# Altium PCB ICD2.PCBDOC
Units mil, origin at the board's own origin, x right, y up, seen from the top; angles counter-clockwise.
Board outline 3890 x 2150 mil, 2 copper layers (Top Layer, Bottom Layer); 55 components, 63 nets, 194 pads, 14 vias.
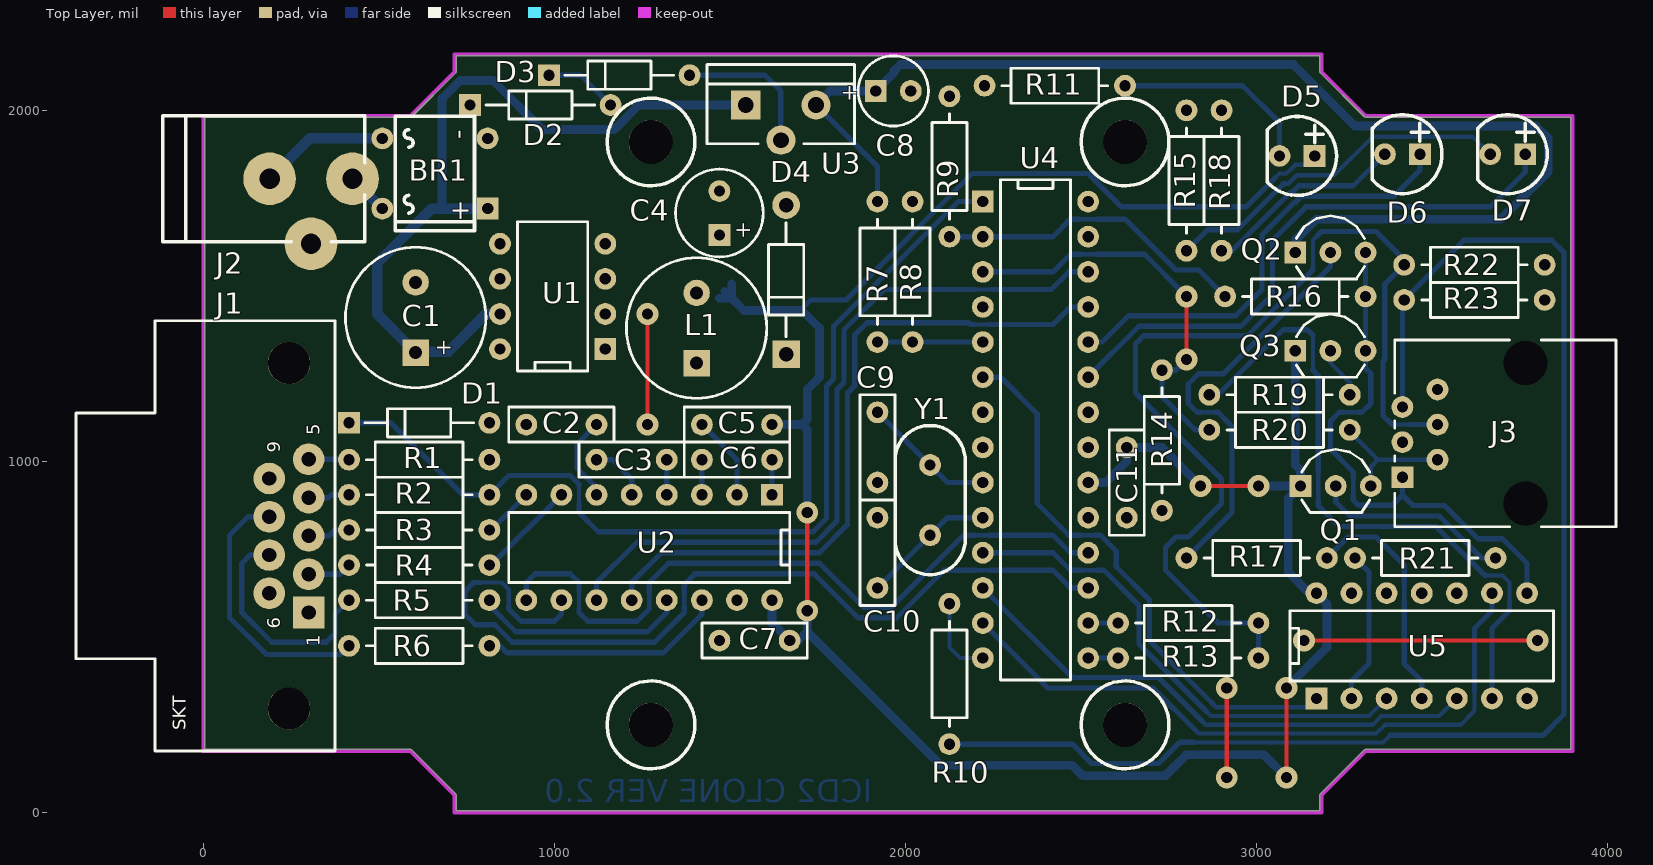
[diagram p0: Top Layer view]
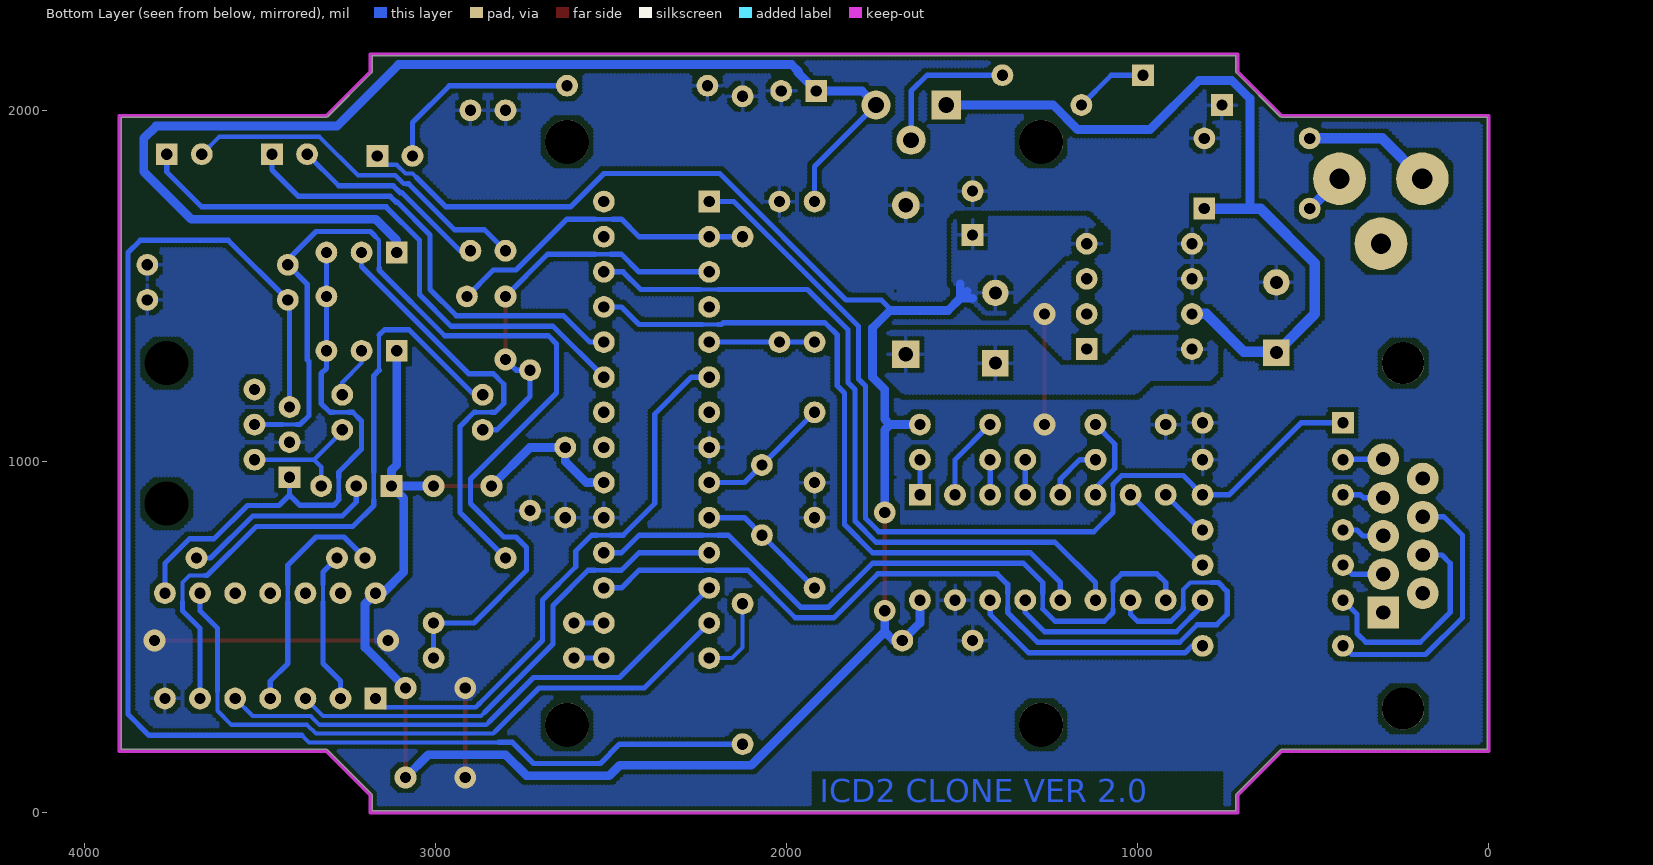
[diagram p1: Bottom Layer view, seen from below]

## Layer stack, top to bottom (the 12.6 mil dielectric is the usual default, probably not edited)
Top Layer: signal copper 1.4
Dielectric: dielectric 12.6, FR-4, Dk 4.8
Bottom Layer: signal copper 1.4

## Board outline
5,180 590,180 593.54,178.54 593.55,178.52 718.52,53.55 718.54,53.54 720,50 720,5 3180,5 3180,50 3181.46,53.54 3181.48,53.55 3306.45,178.52 3306.46,178.54 3310,180 3895,180 3895,1980 3310,1980 3306.46,1981.46 3306.45,1981.48 3181.48,2106.45 3181.46,2106.46 3180,2110 3180,2155 720,2155 720,2110 718.54,2106.46 718.52,2106.45 593.55,1981.48 593.54,1981.46 590,1980 5,1980

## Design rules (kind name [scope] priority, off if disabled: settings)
Clearance [All] p1: gap=12
ComponentClearance [All] p1: gap=10 collisioncheckmode=2
FanoutControl Fanout_Small [All] p1 off: bgadir=Out bgaviamode=Centered fanoutstyle=Auto fanoutdirection=Alternating viagrid=1 // Protel DXP Scope 1 Expression Was: (CompPinCount < 5)   Fanout_Small (Default Rule)
FanoutControl Fanout_Default [All] p2: bgadir=Out bgaviamode=Centered fanoutstyle=Auto fanoutdirection=Alternating viagrid=1 // Fanout_Default (Default Rule)
FanoutControl Fanout_SOIC [All] p3 off: bgadir=Out bgaviamode=Centered fanoutstyle=Auto fanoutdirection=Alternating viagrid=1 // Protel DXP Scope 1 Expression Was: IsSOIC   Fanout_SOIC (Default Rule)
FanoutControl Fanout_BGA [All] p4 off: bgadir=Out bgaviamode=Centered fanoutstyle=Auto fanoutdirection=Alternating viagrid=1 // Protel DXP Scope 1 Expression Was: IsBGA   Fanout_BGA (Default Rule)
FanoutControl Fanout_LCC [All] p5 off: bgadir=Out bgaviamode=Centered fanoutstyle=Auto fanoutdirection=Alternating viagrid=1 // Protel DXP Scope 1 Expression Was: IsLCC   Fanout_LCC (Default Rule)
HoleSize [All] p1: absolutevalues=TRUE maxlimit=150 minlimit=32 maxpercent=80.000 minpercent=20.000
PolygonConnect [All] p1: connectstyle=Relief reliefconductorwidth=10 reliefentries=4 polygonreliefangle="90 Angle"
RoomDefinition ICD2 [InComponentClass('ICD2')] p1: confinementstyle=ConfineIn formatcopy=TRUE outline 5,5 3900,5 3900,2155 5,2155
RoutingLayers [All] p1: top layer=Horizontal bottom layer=Vertical
RoutingVias [All] p1: holewidth=32 width=62 viastyle="Through Hole" minholewidth=28 minwidth=50 maxholewidth=32 maxwidth=62
SolderMaskExpansion [All] p1: expansion=4
TestPointUsage [All] p1: valid=0 allowmultiple=FALSE
Testpoint [All] p1: side=15 testpointundercomponent=TRUE minsize=40 maxsize=100 preferedsize=60 minholesize=0 maxholesize=40 preferedholesize=32 testpointgrid=1 style=1023 order=1234567890
Width [All] p1: maxlimit=50 minlimit=10 preferedwidth=10 toplayer_prefwidth=12 bottomlayer_prefwidth=15 minimp=50.000000 maximp=50.000000 favimp=50.000000
10 further rules are at their usual default settings.

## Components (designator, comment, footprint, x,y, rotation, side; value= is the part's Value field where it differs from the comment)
BR1 "BRIDGE" BRIDGE/DIP4 810,1720 r270 top
C1 "470u" CPCYL1/D.400/LS.200/.037 605,1310 r90 top
C2 "100n" RAD/.300X.100/LS.200/.032 1120,1105 r180 top
C3 "100n" RAD/.300X.100/LS.200/.032 1320,1005 r180 top
C4 "47uF" CPCYL1/D.250/LS.125/.032 1470,1645 r90 top
C5 "100n" RAD/.300X.100/LS.200/.032 1420,1105 r0 top
C6 "100n" RAD/.300X.100/LS.200/.032 1620,1005 r180 top
C7 "100n" RAD/.300X.100/LS.200/.032 1670,490 r180 top
C8 "10u" CPCYL1/D.200/LS.100/.032 1915,2055 r0 top
C9 "22p" RAD/.300X.100/LS.200/.032 1920,1140 r270 top
C10 "22p" RAD/.300X.100/LS.200/.032 1920,640 r90 top
C11 "100n" RAD/.300X.100/LS.200/.032 2630,1040 r270 top
D1 "5.1V" DAX2/.400X.080/.032 815,1110 r0 top
D2 "DIODE" DAX2/.400X.080/.032 1160,2015 r0 top
D3 "DIODE" DAX2/.400X.080/.032 1385,2100 r0 top
D4 "1N5819" DAX2/.425X.100/.041 1660,1730 r90 top
D5 "POWER" LED/ROND/5MM 3165,1870 r0 top
D6 "BUSY" LED/ROND/5MM 3465,1875 r0 top
D7 "ERROR" LED/ROND/5MM 3765,1875 r0 top
J1 "DB9" DSUB/RS.318/TM/9 300,570 r90 top locked
J2 "PJ102A" DC_POWER_JACK 425,1805 r180 top locked
J3 "TARGET" JACK1.27-2V6A 3590,1080 r90 top locked
L1 "220uH" CYL/D.400/LS.200/.037 1405,1280 r90 top
Q1 "2N4403" TO92/100 3125,930 r0 top
Q2 "2N4403" TO92/100 3110,1595 r0 top
Q3 "2N4403" TO92/100 3110,1315 r0 top
R1 "330R" AX/.400X.100/.032 415,1005 r0 top
R2 "1k" AX/.400X.100/.032 815,905 r180 top
R3 "330R" AX/.400X.100/.032 415,805 r0 top
R4 "330R" AX/.400X.100/.032 415,705 r0 top
R5 "330R" AX/.400X.100/.032 415,605 r0 top
R6 "330R" AX/.400X.100/.032 415,475 r0 top
R7 "6k8" AX/.400X.100/.032 1920,1340 r90 top
R8 "2k2" AX/.400X.100/.032 2020,1740 r270 top
R9 "2k2" AX/.400X.100/.032 2125,2040 r270 top
R10 "330R" AX/.400X.100/.032 2125,595 r270 top
R11 "300" AX/.400X.100/.032 2225,2070 r0 top
R12 "330R" AX/.400X.100/.032 2605,540 r0 top
R13 "330R" AX/.400X.100/.032 2605,440 r0 top
R14 "4k7" AX/.400X.100/.032 2730,860 r90 top
R15 "300" AX/.400X.100/.032 2800,2000 r270 top
R16 "6k8" AX/.400X.100/.032 2910,1470 r0 top
R17 "1k2" AX/.400X.100/.032 3200,725 r180 top
R18 "300" AX/.400X.100/.032 2900,2000 r270 top
R19 "390" AX/.400X.100/.032 2865,1190 r0 top
R20 "4k7" AX/.400X.100/.032 2865,1090 r0 top
R21 "130" AX/.400X.100/.032 3280,725 r0 top
R22 "4k7" AX/.400X.100/.032 3820,1560 r180 top
R23 "4k7" AX/.400X.100/.032 3820,1460 r180 top
U1 "LM2594N-5.0" DIP.100/8/W.300/L.425 1145,1320 r90 top
U2 "MAX232A" DIP.100/16/W.300/L.800 1620,905 r180 top
U3 "7812" TO220AB/VF1 1545,2015 r0 top
U4 "PIC16F876A" DIP.100/28/W.300/L1.425 2220,1740 r270 top
U5 "SN74LS07N" DIP.100/14/W.300/L.750 3170,325 r0 top
Y1 "20MHz" XTAL/HC49 2070,790 r90 top

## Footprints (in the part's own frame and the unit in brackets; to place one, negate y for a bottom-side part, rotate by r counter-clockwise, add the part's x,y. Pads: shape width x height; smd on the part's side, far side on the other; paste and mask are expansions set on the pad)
AX/.400X.100/.032 [mil]
  round 62 hole 32: 1(0,0) 2(400,0)
  silkscreen extent 50,-50 350,50
BRIDGE/DIP4 [mil]
  round 62 hole 32: AC1(-200,-300) AC2(0,-300) V-(-200,0)
  rect 62x62 hole 32: V+(0,0)
  silkscreen extent -262,-263 63,-37
CPCYL1/D.200/LS.100/.032 [mil]
  rect 62x62 hole 32: 1(0,0)
  round 62 hole 32: 2(100,0)
  silkscreen extent -50,-100 150,100
CPCYL1/D.250/LS.125/.032 [mil]
  rect 62x62 hole 32: 1(0,0)
  round 62 hole 32: 2(125,0)
  silkscreen extent -62,-125 188,125
CPCYL1/D.400/LS.200/.037 [mil]
  rect 75x75 hole 37: 1(0,0)
  round 75 hole 37: 2(200,0)
  silkscreen extent -100,-200 300,200
CYL/D.400/LS.200/.037 [mil]
  rect 75x75 hole 37: 1(0,0)
  round 75 hole 37: 2(200,0)
  silkscreen extent -100,-200 300,200
DAX2/.400X.080/.032 [mil]
  round 62 hole 32: 1(0,0)
  rect 62x62 hole 32: 2(-400,0)
  silkscreen extent -355,-40 -45,40
DAX2/.425X.100/.041 [mil]
  round 79 hole 41: 1(0,0)
  rect 79x79 hole 41: 2(-425,0)
  silkscreen extent -375,-50 -50,50
DC_POWER_JACK [mil]
  round 150 hole 58: 1(0,0) 2(236,0) 3(118,185)
  silkscreen extent -35,-180 540,180
DIP.100/8/W.300/L.425 [mil]
  rect 62x62 hole 32: 1(0,0)
  round 62 hole 32: 2(100,0) 3(200,0) 4(300,0) 5(300,300) 6(200,300) 7(100,300) 8(0,300)
  silkscreen extent -63,50 362,250
DIP.100/14/W.300/L.750 [mil]
  rect 62x62 hole 32: 1(0,0)
  round 62 hole 32: 2(100,0) 3(200,0) 4(300,0) 5(400,0) 6(500,0) 7(600,0) 8(600,300) 9(500,300) 10(400,300) 11(300,300) 12(200,300) 13(100,300) 14(0,300)
  silkscreen extent -75,50 675,250
DIP.100/16/W.300/L.800 [mil]
  rect 62x62 hole 32: 1(0,0)
  round 62 hole 32: 2(100,0) 3(200,0) 4(300,0) 5(400,0) 6(500,0) 7(600,0) 8(700,0) 9(700,300) 10(600,300) 11(500,300) 12(400,300) 13(300,300) 14(200,300) 15(100,300) 16(0,300)
  silkscreen extent -50,50 750,250
DIP.100/28/W.300/L1.425 [mil]
  rect 62x62 hole 32: 1(0,0)
  round 62 hole 32: 2(100,0) 3(200,0) 4(300,0) 5(400,0) 6(500,0) 7(600,0) 8(700,0) 9(800,0) 10(900,0) 11(1000,0) 12(1100,0) 13(1200,0) 14(1300,0) 15(1300,300) 16(1200,300) 17(1100,300) 18(1000,300) 19(900,300) 20(800,300) 21(700,300) 22(600,300) 23(500,300) 24(400,300) 25(300,300) 26(200,300) 27(100,300) 28(0,300)
  silkscreen extent -63,50 1362,250
DSUB/RS.318/TM/9 [mil]
  rect 90x90 hole 41: 1(0,0)
  round 90 hole 41: 2(109,0) 3(218,0) 4(327,0) 5(436,0) 6(54.5,112) 7(163.5,112) 8(272.5,112) 9(381.5,112)
  round 120 hole 120: 10(-274,56) 11(710,56)
  silkscreen extent -394,-76 830,662
JACK1.27-2V6A [mil]
  rect 62x62 hole 32: 1(-125,175)
  round 62 hole 32: 2(-75,75) 3(-25,175) 4(25,75) 5(75,175) 6(125,75)
  round 116.14 hole 125: MH1(-200,-175) MH2(200,-175)
  silkscreen extent -266,-433 266,197
LED/ROND/5MM [mil]
  rect 62x62 hole 32: 1(0,0)
  round 62 hole 32: 2(-100,0)
  silkscreen extent -135,-112 62,112
RAD/.300X.100/LS.200/.032 [mil]
  round 62 hole 32: 1(0,0) 2(200,0)
  silkscreen extent -50,-50 250,50
TO92/100 [mil]
  rect 62x62 hole 32: 1(0,0)
  round 62 hole 32: 2(100,0) 3(200,0)
  silkscreen extent 3,-75 197,105
TO220AB/VF1 [mil]
  rect 83x83 hole 45: 1(0,0)
  round 83 hole 45: 2(100,-100) 3(200,0)
  silkscreen extent -110,-110 310,115
XTAL/HC49 [mil]
  round 62 hole 32: 1(0,0) 2(200,0)
  silkscreen extent -112,-100 312,100

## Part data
BR1: "PONT DE DIODE"
C1 C4 C8: library part CE, "CONDO ELECT POLARISE DE BASE"
C2 C3 C5 C6 C7 C9 C10 C11: library part CC, "CONDO CERAMIQUE DE BASE"
D1: library part ZENER, "DIODE ZENER"
D4: library part SCHOTTKY, "DIODE SCHOTTKY"
D5 D6 D7: library part LED, "LED RONDE OU RECTANGULAIRE"
J1: library part CON9, "CONNECTEUR 9 PINS"
J2: library part CON2, "CONNECTEUR 2 PINS"
J3: library part CON6, "CONNECTEUR 6 PINS"
L1: library part INDUCTANCE, "INDUCTANCE"
Q1 Q2 Q3: library part 2N3906, "PNP General Purpose Amplifier"
R1 R2 R3 R4 R5 R6 R7 R8 R9 R10 R11 R12 R13 R14 R15 R16 R17 R18 R19 R20 R21 R22 R23: library part R1/4W, "RESISTANCE 1/4W LS=.4\""
U1: "Simple Switcher Power Converter 150 kHz 0.5A Step Down Voltage Regulator"
U2: library part MAX232
U3: library part REG/POS/TO220, "REGULATEUR POSITIF TO220"
U5: "Hex Buffer / Driver with Open-Collector High-Voltage Outputs"
Y1: library part CRYSTAL, "CRYSTAL"

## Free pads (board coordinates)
  round 125 hole 125 unplated: MH1(1275,1910) MH2(1275,250) MH3(2625,250) MH4(2625,1910)

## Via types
v1: diameter 62, hole 32, Top Layer to Bottom Layer, 14 vias

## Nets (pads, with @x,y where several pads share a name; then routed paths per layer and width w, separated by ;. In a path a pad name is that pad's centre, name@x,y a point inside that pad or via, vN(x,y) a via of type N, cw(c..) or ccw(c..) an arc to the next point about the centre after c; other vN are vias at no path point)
+V: BR1.V+ C1.1 U1.7 U3.1 | length 2257.9
  Bottom Layer w25: 680,1720 680,2033.28 731.72,2085 825,2085 965,1945 1170,1945 1240,2015 U3.1
  Bottom Layer w30: BR1.V+ 680,1720 650,1720 495,1565 495,1420 C1.1@602.08,1312.92 ; U1.7 805,1420 697.92,1312.92 C1.1@607.92,1312.92 ; C1.1@602.08,1312.92 C1.1 C1.1@607.92,1312.92 ; C1.1@602.08,1312.92 605,1312.92 C1.1@607.92,1312.92
CTS: J1.7 R5.1 | length 649.9
  Bottom Layer w15: J1.7 133.5,733.5 110,710 110,570 195,485 350,485 375,510 375,565 R5.1
"DTE READY": J1.4 R2.2 | length 118.3
  Bottom Layer w15: J1.4 357,897 365,905 R2.2
GND: BR1.V- C1.2 C2.2 C4.2 C7.2 C8.2 C9.2 C10.2 C11.2 D1.1 D2.2 D4.1 J3.3 R1.2 R8.1 R9.1 R11.1 R14.1 R15.1 R18.1 R22.1 R23.1 U1.5 U1.6 U2.15 U4.8 U4.19 U5.7 | length 1235
  Top Layer w12: v1(1265,1105) v1(1265,1420) ; v1(2915,100) v1(2915,355) ; v1(3135,490) v1(3800,490)
GND-232: J1.5 R1.1 | length 115.4
  Bottom Layer w12: R1.1@414,1006 R1.1
  Bottom Layer w15: J1.5 R1.1@414,1006
ICD-VDD: J3.2 Q1.3 R20.2 | length 371.4
  Bottom Layer w12: R20.2 3265,1085 3345,1005 ; Q1.3 3325,985 3345,1005 ; J3.2 3345,1005
ICD-VPP: J3.1 Q2.3 Q3.3 R16.2 U5.8 | length 1558.3
  Bottom Layer w12: 3245,1140 3290,1140 ; 3275,905 3275,955
  Bottom Layer w15: 3245,1140 3235,1140 3210,1115 3210,1035 3275,970 3275,955 ; 3275,905 3275,890 3290,875 3385,875 3415,905 ; 3290,1140 3300,1140 3325,1165 3325,1250 3310,1265 Q3.3 R16.2 Q2.3 Q2.3@3310,1600 ; J3.1 3415,905 ; U5.8 3770,710 3700,780 3630,780 3535.12,874.88 3445.12,874.88 3415,905
MCLR: D1.2 R2.1 U4.1 | length 2728.8
  Bottom Layer w12: 1070,880 1070,935
  Bottom Layer w15: D1.2 535,1110 740,905 R2.1 870,960 1045,960 1070,935 1070,930 ; 1070,880 1070,855 1125,800 1736.82,800 1775,838.18 1775,1214.75 1795,1234.75 1795,1385 2150,1740 U4.1
NetBR1_AC1: BR1.AC1 J2.2 | length 368.6
  Bottom Layer w30: J2.2 304,1920 BR1.AC1
NetBR1_AC2: BR1.AC2 J2.1 | length 120.2
  Bottom Layer w30: J2.1 BR1.AC2
NetC2_1: C2.1 U2.6 | length 245.6
  Bottom Layer w15: U2.6 1120,925 1065,980 1065,1050 C2.1
NetC3_1: C3.1 U2.4 | length 100
  Bottom Layer w15: U2.4 C3.1
NetC3_2: C3.2 U2.5 | length 167.8
  Bottom Layer w15: C3.2 1165,1005 1220,950 U2.5
NetC5_1: C5.1 U2.2 | length 241.4
  Bottom Layer w15: C5.1 1520,1005 U2.2
NetC6_1: C6.1 U2.1 | length 100
  Bottom Layer w15: U2.1 C6.1
NetC6_2: C6.2 U2.3 | length 100
  Bottom Layer w15: U2.3 C6.2
NetC9_1: C9.1 U4.9 Y1.2 | length 387.8
  Bottom Layer w15: C9.1 Y1.2 ; Y1.2@2070,995 Y1.2 ; U4.9 2120,940 Y1.2
NetC10_1: C10.1 U4.10 Y1.1 | length 382.8
  Bottom Layer w15: C10.1 Y1.1 2120,840 U4.10
NetD2_1: D2.1 D3.2 | length 210.2
  Bottom Layer w15: D3.2 1075,2100 D2.1
NetD3_1: D3.1 U3.2 | length 418.6
  Bottom Layer w15: D3.1 1600,2100 1645,2055 U3.2
NetD4_2: D4.2 L1.1 U1.8
NetD5_2: D5.2 R11.2 | length 578.5
  Bottom Layer w15: R11.2 2960,2070 3065,1965 D5.2
NetD6_2: D6.2 R18.2 | length 586
  Bottom Layer w12: R18.2@2900,1595 2902.5,1597.5 R18.2@2905,1600
  Bottom Layer w15: R18.2 2905,1600 2930,1600 3095.5,1765.5 3100.5,1765.5 3120,1785 3275,1785 D6.2
NetD7_2: D7.2 R15.2 | length 1019.9
  Bottom Layer w12: 3081,1791 3089.94,1791 3113.94,1815 3220,1815 3329.5,1924.5 3615.5,1924.5 D7.2
  Bottom Layer w15: R15.2 2860,1660 2945,1660 3076,1791 3081,1791
NetJ3_6: J3.6
NetQ1_2: Q1.2 R21.2 | length 586.3
  Bottom Layer w15: Q1.2 3225,885 3265,845 3520,845 3640,725 R21.2 R21.2@3700,725
NetQ2_2: Q2.2 R17.2 | length 1224.5
  Bottom Layer w12: 2840,1140 2890,1140
  Bottom Layer w15: R17.2 2930,855 2930,1100 2890,1140 2885,1140 ; 2840,1140 2830,1140 2805,1165 2805,1220 2835,1250 2905,1250 3210,1555 Q2.2
NetQ3_2: Q3.2 R19.2 | length 147.8
  Bottom Layer w12: Q3.2 3210,1280 3265,1225 R19.2
NetR3_2: R3.2 U2.8 | length 151.4
  Bottom Layer w12: U2.8@915,905 U2.8
  Bottom Layer w15: R3.2 820,805 U2.8
NetR4_2: R4.2 U2.7 | length 292.8
  Bottom Layer w12: U2.7@1015,905 U2.7
  Bottom Layer w15: R4.2 820,705 U2.7
NetR5_2: R5.2 U2.13 | length 628
  Bottom Layer w12: R5.2@815,600 R5.2 R5.2@817.5,602.5 ; U2.13 U2.13@1325,600
  Bottom Layer w15: R5.2 R5.2@815,600 ; R5.2@817.5,602.5 R5.2@815,600 ; U2.13 1320,570 1265,515 890,515 815,590 R5.2@815,600
NetR6_2: R6.2 U2.14 | length 698.8
  Bottom Layer w15: R6.2 845,475 865,455 1310,455 1420,565 U2.14
NetR17_1: R17.1 U5.4 | length 678.7
  Bottom Layer w12: 3420,600 3420,650
  Bottom Layer w15: R17.1 3260,785 3340,785 3420,705 3420,650 ; 3420,600 3420,425 3470,375 U5.4
NetR19_1: R19.1 U5.6 | length 1855.9
  Bottom Layer w12: 3160,1260 3160,1360 ; 3175,890 3175,970 ; 3655,675 3700,675 3720,655 3720,600
  Bottom Layer w15: R19.1 2890,1190 3075,1375 3145,1375 3160,1360 ; 3160,1260 3175,1245 3175,970 ; 3175,890 3175,875 3235,815 3510,815 3650,675 3655,675 ; U5.6 3670,525 3720,575 3720,600
NetR21_1: R21.1 U5.2 | length 437.3
  Bottom Layer w12: 3320,600 3320,650
  Bottom Layer w15: U5.2 3270,375 3320,425 3320,600 ; R21.1 3320,685 3320,650
NetU1_1: U1.1
NetU1_2: U1.2
NetU1_3: U1.3
NetU4_7: U4.7
PGC: J3.5 R10.2 R23.2 | length 4226.1
  Bottom Layer w12: 2820,200 3360,200 3380,220 ; R23.2 3585,1625
  Bottom Layer w15: R10.2 2475,195 2530,140 2720,140 2780,200 2820,200 ; 3380,220 3815,220 3875,280 3875,1595 3840,1630 3590,1630 R23.2 3415,1455 J3.5
PGD: J3.4 R12.2 R13.2 R22.2 | length 2861.1
  Bottom Layer w12: 3160,1550 3160,1630 3171.6,1641.6 ; 3395,1105 3435,1105
  Bottom Layer w15: R13.2 R12.2 2890,540 2740,690 2740,755 2770,785 2805,785 2900,880 2900,950 2655,1195 2655,1335 2678,1358 2973,1358 3160,1545 3160,1550 ; 3171.6,1641.6 3185,1655 3340,1655 R22.2@3420,1575 ; 3395,1105 3385,1105 3360,1130 3360,1285 3365,1290 3365,1505 R22.2 ; 3435,1105 J3.4
RA0: R9.2 R16.1 U4.2 | length 896.8
  Bottom Layer w12: 2495,1690 2545,1690
  Bottom Layer w15: R9.2 U4.2 2420,1640 2470,1690 2495,1690 ; 2545,1690 2625,1690 2770,1545 2835,1545 R16.1
RA1: R14.2 R20.1 U4.3 | length 1172.2
  Top Layer w12: v1(2800,1290) v1(2800,1470)
  Bottom Layer w12: U4.3 U4.3@2220,1545 ; 2500,1590 2545,1590 ; R14.2 R14.2@2735,1260
  Bottom Layer w15: U4.3 2420,1540 2470,1590 2500,1590 ; 2545,1590 2680,1590 v1(2800,1470) ; v1(2800,1290) 2770,1260 R14.2 2730,1185 2825,1090 R20.1
RA3: R7.1 R8.2 U4.5 | length 305
  Top Layer w12: R7.1@1925,1340 R7.1@1930,1340
  Bottom Layer w15: R7.1 R8.2 U4.5
RA4: U4.6 U5.1 | length 1592.8
  Bottom Layer w12: 2500,790 2540,790 ; 2875,310 2885,300 3145,300 U5.1
  Bottom Layer w15: U4.6 2270,1240 2375,1135 2375,880 2465,790 2500,790 ; 2540,790 2555,790 2600,745 2600,700 2695,605 2695,490 2875,310
RB2-ERROR: D7.1 U4.23 | length 1628.1
  Bottom Layer w15: U4.23 2665,1385 2955,1385 3045,1475 3045,1630 3140,1725 3665,1725 3765,1825 D7.1
RB3-BUSY: D6.1 U4.24 | length 1283.8
  Bottom Layer w15: U4.24 2560,1340 2635,1415 2940,1415 3015,1490 3015,1645 3108.5,1738.5 3111.69,1738.5 3128.19,1755 3390,1755 3465,1830 D6.1
RB4-CTS: U2.12 U4.25 | length 1983.9
  Bottom Layer w12: 2195,1390 2240,1390
  Bottom Layer w15: U2.12 1220,655 1305,740 1755,740 1835,820 1835,1195 1855,1215 1855,1360 1890,1395 2180,1395 2185,1390 2195,1390 ; 2240,1390 2420,1390 2470,1440 U4.25
RB5-RTS: U2.11 U4.26 | length 2124.1
  Bottom Layer w12: 2195,1490 2245,1490
  Bottom Layer w15: U2.11 1120,655 1235,770 1745,770 1805,830 1805,1205 1825,1225 1825,1375 1940,1490 2195,1490 ; 2245,1490 2415,1490 2465,1540 U4.26
RC0: U4.11 U5.3 | length 1427.8
  Bottom Layer w12: 2500,690 2545,690 ; 2860,285 2870,275 3320,275 U5.3
  Bottom Layer w15: U4.11 2420,740 2470,690 2500,690 ; 2545,690 2565,690 2665,590 2665,480 2860,285
RC1: U4.12 U5.5 | length 1550.4
  Bottom Layer w12: 2841.67,263.33 2855,250 3330,250 3355,275 3520,275 U5.5
  Bottom Layer w15: U4.12 2475,385 2720,385 2847.21,257.79
RC2: U4.13 U5.9 | length 1913.1
  Bottom Layer w12: 2827.9,232.1 2835,225 3340,225 3365,250 3580,250 3620,290 3620,345
  Bottom Layer w15: U4.13 2405,355 2705,355 2827.9,232.1 ; 3620,345 3620,525 3670,575 U5.9
RC3: R10.1 U4.14 | length 232.4
  Bottom Layer w12: R10.1 2125,470 2155,440 U4.14
RC4: R13.1 U4.15 | length 105
  Bottom Layer w12: R13.1 R13.1@2625,440
  Bottom Layer w15: U4.15 R13.1
RC5: R12.1 U4.16 | length 105
  Bottom Layer w12: R12.1 R12.1@2625,540
  Bottom Layer w15: U4.16 R12.1
RC6-TX: U2.10 U4.17 | length 2540.6
  Bottom Layer w12: 790,655 850,655 870,635 870,585 ; 1370,585 1370,625 ; 2200,690 2240,690
  Bottom Layer w15: 790,655 770,655 745,630 745,565 775,535 830,535 880,485 1285,485 1370,570 1370,585 ; 870,585 870,580 905,545 1000,545 1020,565 U2.10 ; 1370,625 1370,650 1400,680 1740,680 1865,555 1975,555 2110,690 2200,690 ; 2240,690 2420,690 2470,640 U4.17
RC7-RX: U2.9 U4.18 | length 2035.7
  Bottom Layer w12: 1070,580 1070,630 ; 1270,580 1270,625 ; 2195,790 2240,790
  Bottom Layer w15: U2.9 920,655 945,680 1045,680 1070,655 1070,630 ; 1070,580 1070,570 1095,545 1235,545 1270,580 ; 1270,625 1270,655 1325,710 1755,710 1880,585 1960,585 2165,790 2195,790 ; 2240,790 2420,790 2470,740 U4.18
RE2: 
RTS: J1.8 R6.1 | length 763.6
  Bottom Layer w15: J1.8 127.5,842.5 75,790 75,555 180,450 390,450 R6.1
RX-231: J1.3 R3.1 | length 122
  Bottom Layer w15: J1.3 358,788 375,805 R3.1
TX-232: J1.2 R4.1 | length 125.8
  Bottom Layer w15: J1.2 389,679 R4.1
VCC: C4.1 C5.2 C7.1 C11.1 D5.1 L1.2 Q1.1 Q3.1 U1.4 U2.16 U4.20 U5.14 | length 6915.1
  Top Layer w12: v1(1720,575) v1(1720,855) ; v1(2840,930) v1(3005,930) ; v1(3085,100) v1(3085,355)
  Bottom Layer w12: 1700,1430 1705,1435 ; 3053.16,1808.16 3065,1820 3085,1820 3110,1845 3140,1845 D5.1
  Bottom Layer w15: 1705,1430 1705,1435 1730,1460 1830,1460 2190,1820 2520,1820 2615,1725 2970,1725 3053.16,1808.16
  Bottom Layer w25: 1470,1465 1505,1465 ; 1485,1485 1505,1465 ; 1505,1505 1505,1465 ; U2.16 1620,540 C7.1 1695,490 1720,515 ; C5.2 1705,1105 ; v1(1720,575) 1720,515 ; v1(1720,855) 1720,1090 1705,1105 ; U4.20 2570,940 2630,1000 C11.1 2730,1040 v1(2840,930) ; v1(3005,930) Q1.1 ; v1(3085,100) 3020,165 2800,165 2740,105 2505,105 2475,135 2100,135 1720,515 ; v1(3085,355) 3200,470 3200,595 U5.14 ; Q3.1 3110,990 3125,975 Q1.1 ; U5.14@3150,625 3090,685 3090,895 Q1.1 ; 1505,1465 1540,1430 1700,1430 1705,1430 1755,1380 1755,1240 1720,1205 1720,1120 1705,1105
VPP: C8.1 Q2.1 R7.2 U3.3 | length 3509.8
  Top Layer w25: C8.1 C8.1@1915,2060
  Bottom Layer w15: U3.3 1920,1840 R7.2
  Bottom Layer w25: U3.3 1785,2055 C8.1 ; C8.1@1920,2055 C8.1 ; 1965,2110 1985.5,2130.5 3104.5,2130.5 3280,1955 3795,1955 3830,1920 3830,1825 3695,1690 3170,1690 3110,1630 Q2.1 ; 1967.5,2107.5 C8.1
pads on no net: J1.1 J1.6 J1.9 J1.10 J1.11 J2.3 J3.MH1 J3.MH2 U4.4 U4.21 U4.22 U4.27 U4.28 U5.10 U5.11 U5.12 U5.13

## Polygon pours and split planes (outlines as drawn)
GND on Bottom Layer (hatched 90Degree grid 10 track 12, remove dead copper): 0,0 3900,0 3900,2160 0,2160
GND on Bottom Layer (hatched 90Degree grid 5 track 10, remove dead copper): 1630,1670 1580,1720 1125,1720 1095,1690 885,1480 805,1480 775,1450 570,1450 545,1475 545,1540 575,1570 715,1570 815,1670 910,1670 1065,1825 1655,1825 1720,1760 1720,1700 1690,1670
VCC on Bottom Layer (hatched 90Degree grid 10 track 12, remove dead copper): 1430,1420 1380,1420 1210,1590 1110,1590 1095,1605 1095,1645 1145,1695 1510,1695 1525,1680 1525,1510 1435,1420
NetD4_2 on Bottom Layer (hatched 90Degree grid 10 track 12, remove dead copper): 805,1355 1010,1355 1095,1270 1220.03,1270.03 1320,1370 1705,1370 1720,1355 1720,1250 1665,1195 1005,1195 965,1235 795,1235 775,1255 775,1325

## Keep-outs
Keep-Out Layer:
  lines w10: 0,175 0,1985 590,1985 715,2110 715,2160 3185,2160 3185,2110 3310,1985 3900,1985 3900,175 3310,175 3185,50 3185,0 715,0 715,50 590,175 0,175

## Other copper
Bottom Layer:
  text "ICD2 CLONE VER 2.0" at 1905,30 h65

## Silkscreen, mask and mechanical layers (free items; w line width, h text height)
Top Overlay:
  circle w10: c2625,250 r125
  circle w10: c2625,1910 r125
  circle w10: c1275,1910 r125
  circle w10: c1275,250 r125
Board Outline:
  lines w10: 715,0 715,50 590,175 0,175 0,1985 590,1985 714.4,2109.4 714.4,2160.14 3184.86,2160.14 ; 715.14,-0.14 3185.6,-0.14 3185.6,50.6 3310,175 3500,175 ; 3185,2160 3185,2110 3310,1985 3500,1985 ; 3490,175 3900,175 3900,1985 3490,1985
Dimensions:
  lines w10: -250,0 -150,0 ; -250,2160 -150,2160 ; -220,60 -200,0 ; -220,2100 -200,2160 ; -200,804.08 -200,0 ; -200,1355.92 -200,2160 ; -180,60 -200,0 ; -180,2100 -200,2160 ; 0,-150 0,-50 ; 60,-120 0,-100 ; 60,-80 0,-100 ; 1669.09,-100 0,-100 ; 2230.91,-100 3900,-100 ; 3840,-120 3900,-100 ; 3840,-80 3900,-100 ; 3900,-150 3900,-50
  text "2160 (mil)" at -164.01,814.08 h60 r90
  text "3900 (mil)" at 1679.09,-135.99 h60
